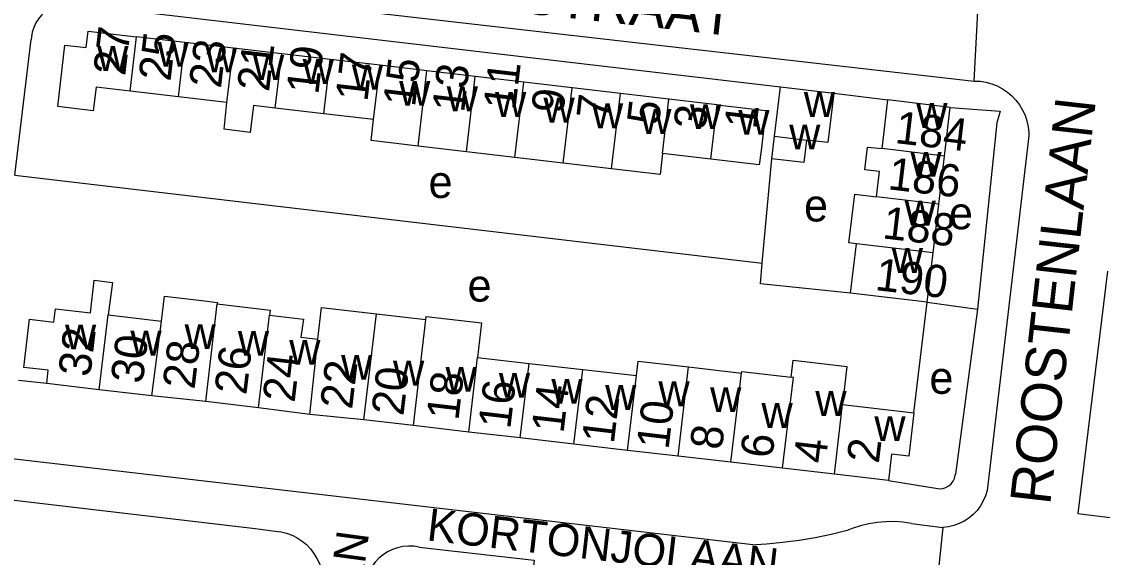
# Model space of a CAD drawing. Extents: x 161258 to 163262, y 380749 to 382054.
# Drawn here: x 162145.4 to 162279.3, y 380909.2 to 380975.6 of the extents above; entities that cross this region are included whole.
import ezdxf

# ---------------------------------------------------------------- set-up
doc = ezdxf.new("R2010")
doc.units = 0
for name, color, linetype in [('BLT_Basislijn', 7, 'Continuous'), ('BLT_Bebouwing', 7, 'Continuous'), ('BLT_Centroide', 7, 'Continuous'), ('BLT_Huisnummer', 7, 'Continuous'), ('BLT_Huisnummer_ tussenligend', 7, 'Continuous'), ('BLT_Onderverdeling_panden', 7, 'Continuous'), ('BLT_Straatnaam', 7, 'Continuous'), ('BLT_Straatnaam_verkleind', 7, 'Continuous'), ('BLT_Vlakafsluiter', 7, 'Continuous')]:
    doc.layers.add(name, color=color, linetype=linetype)

msp = doc.modelspace()

# ---------------------------------------------------------------- linework, layer by layer
at = {"layer": 'BLT_Basislijn'}
for p, q in [((162149.69, 380981.18), (162263.4, 380968.19)), ((162151.72, 380977.74), (162239.4, 380967.48)), ((162144.57, 380956.51), (162146.6, 380973.32)), ((162246, 380966.69), (162252.7, 380965.85)), ((162270.17, 380961.38), (162264.99, 380917.45)), ((162237.15, 380945.62), (162238.35, 380958.55)), ((162144.57, 380956.51), (162237.15, 380945.62)), ((162255.92, 380927.07), (162257.58, 380940.78)), ((162257.58, 380940.78), (162263.8, 380939.93)), ((162263.8, 380939.93), (162261.07, 380919.46)), ((162148.51, 380930.7), (162145, 380931.06)), ((162137.75, 380922.16), (162236.36, 380910.73)), ((162252.79, 380918.69), (162259.13, 380917.67)), ((162129.01, 380918.07), (162174.34, 380912.72)), ((162255.62, 380913.38), (162259.51, 380912.85)), ((162174.34, 380912.72), (162176.83, 380912.42))]:
    msp.add_line(p, q, dxfattribs=at)
for points in [[(162151.72, 380977.74), (162151.12, 380977.77), (162150.51, 380977.73), (162149.92, 380977.6), (162149.35, 380977.39), (162148.81, 380977.12), (162148.32, 380976.77), (162147.87, 380976.36), (162147.48, 380975.9), (162147.15, 380975.39), (162146.9, 380974.84), (162146.72, 380974.26), (162146.62, 380973.67), (162146.6, 380973.32)], [(162263.4, 380968.19), (162264.13, 380968.16), (162264.86, 380968.04), (162265.57, 380967.85), (162266.25, 380967.58), (162266.9, 380967.24), (162267.51, 380966.82), (162268.07, 380966.35), (162268.57, 380965.82), (162269.01, 380965.23), (162269.39, 380964.6), (162269.7, 380963.94), (162269.93, 380963.24), (162270.09, 380962.53), (162270.16, 380961.8), (162270.17, 380961.38)], [(162260.44, 380964.93), (162266.6, 380964.46), (162266.21, 380963.03), (162263.8, 380939.93)], [(162248.07, 380941.9), (162236.91, 380943.04), (162237.15, 380945.62)], [(162279.93, 380944.61), (162276.25, 380914.58), (162303.55, 380911.22)], [(162259.13, 380917.67), (162259.52, 380917.71), (162259.9, 380917.83), (162260.24, 380918.03), (162260.54, 380918.28), (162260.78, 380918.6), (162260.96, 380918.95), (162261.05, 380919.34), (162261.07, 380919.46)], [(162264.99, 380917.45), (162264.79, 380916.79), (162264.51, 380916.15), (162264.16, 380915.55), (162263.75, 380914.99), (162263.27, 380914.49), (162262.74, 380914.04), (162262.16, 380913.66), (162261.54, 380913.35), (162260.89, 380913.1), (162260.22, 380912.94), (162259.51, 380912.85)], [(162255.62, 380913.38), (162254.57, 380913.53), (162253.51, 380913.6), (162252.44, 380913.58), (162251.38, 380913.49), (162250.33, 380913.32), (162249.3, 380913.07), (162248.29, 380912.74), (162247.67, 380912.5)], [(162176.83, 380912.42), (162177.54, 380912.33), (162178.23, 380912.16), (162178.9, 380911.91), (162179.54, 380911.58), (162180.14, 380911.19), (162180.69, 380910.74), (162181.19, 380910.22), (162181.62, 380909.65), (162181.99, 380909.04), (162182.29, 380908.39), (162182.52, 380907.71), (162182.67, 380907.01), (162182.74, 380906.3), (162182.73, 380905.69)], [(162247.67, 380912.5), (162245.7, 380912), (162243.71, 380911.59), (162241.71, 380911.25), (162239.7, 380910.99), (162237.67, 380910.81), (162236.36, 380910.73)], [(162194.65, 380910.44), (162193.98, 380910.54), (162193.31, 380910.56), (162192.64, 380910.49), (162191.98, 380910.35), (162191.34, 380910.13), (162190.74, 380909.84), (162190.17, 380909.48), (162189.65, 380909.05), (162189.19, 380908.56), (162188.78, 380908.03), (162188.44, 380907.44), (162188.18, 380906.83), (162187.99, 380906.18), (162187.87, 380905.52), (162187.84, 380904.85), (162187.86, 380904.41)], [(162194.65, 380910.44), (162208.89, 380908.83), (162208.71, 380907.24), (162226.2, 380904.94), (162226.56, 380906.89), (162234.68, 380905.82), (162237.16, 380905.82)]]:
    msp.add_lwpolyline(points, dxfattribs=at)
at = {"layer": 'BLT_Bebouwing'}
for p, q in [((162165.63, 380972.97), (162159.64, 380973.67)), ((162171.63, 380972.27), (162165.63, 380972.97)), ((162177.62, 380971.57), (162171.63, 380972.27)), ((162183.62, 380970.87), (162177.62, 380971.57)), ((162189.8, 380970.14), (162183.62, 380970.87)), ((162195.61, 380969.46), (162189.8, 380970.14)), ((162201.6, 380968.76), (162195.61, 380969.46)), ((162207.6, 380968.06), (162201.6, 380968.76)), ((162213.59, 380967.36), (162207.6, 380968.06)), ((162164.84, 380966.24), (162158.85, 380966.94)), ((162219.59, 380966.66), (162213.59, 380967.36)), ((162225.58, 380965.95), (162219.59, 380966.66)), ((162238.68, 380961.34), (162239.4, 380967.48)), ((162239.4, 380967.48), (162246, 380966.69)), ((162170.84, 380965.54), (162164.84, 380966.24)), ((162231.58, 380965.25), (162225.58, 380965.95)), ((162260.44, 380964.93), (162252.7, 380965.85)), ((162182.83, 380964.14), (162176.83, 380964.84)), ((162189.01, 380963.41), (162182.83, 380964.14)), ((162259.72, 380958.9), (162260.44, 380964.93)), ((162238.35, 380958.55), (162238.68, 380961.34)), ((162200.51, 380959.43), (162194.51, 380960.13)), ((162206.5, 380958.73), (162200.51, 380959.43)), ((162212.5, 380958.03), (162206.5, 380958.73)), ((162230.79, 380958.52), (162224.79, 380959.22)), ((162259.02, 380952.92), (162259.72, 380958.9)), ((162218.49, 380957.33), (162212.5, 380958.03)), ((162258.3, 380946.89), (162259.02, 380952.92)), ((162248.07, 380941.9), (162248.8, 380948.02)), ((162257.58, 380940.78), (162258.3, 380946.89)), ((162156.12, 380939.21), (162162.73, 380938.43)), ((162189.35, 380939.34), (162195.49, 380938.63)), ((162201.87, 380933.94), (162208.26, 380933.2)), ((162208.26, 380933.2), (162214.9, 380932.44)), ((162214.9, 380932.44), (162221.55, 380931.68)), ((162228, 380932.76), (162234.58, 380932)), ((162155.02, 380929.93), (162148.51, 380930.7)), ((162161.54, 380929.16), (162155.02, 380929.93)), ((162168.21, 380928.46), (162161.54, 380929.16)), ((162174.76, 380927.71), (162168.21, 380928.46)), ((162247.1, 380928.11), (162255.92, 380927.07)), ((162181.09, 380926.85), (162174.76, 380927.71)), ((162187.8, 380926.2), (162181.09, 380926.85)), ((162193.94, 380925.49), (162187.8, 380926.2)), ((162200.78, 380924.69), (162193.94, 380925.49)), ((162207.17, 380923.96), (162200.78, 380924.69)), ((162213.81, 380923.19), (162207.17, 380923.96)), ((162220.46, 380922.42), (162213.81, 380923.19)), ((162226.72, 380921.69), (162220.46, 380922.42)), ((162233.24, 380920.94), (162226.72, 380921.69)), ((162239.67, 380920.2), (162233.24, 380920.94)), ((162246.08, 380919.46), (162239.67, 380920.2)), ((162252.79, 380918.69), (162246.08, 380919.46))]:
    msp.add_line(p, q, dxfattribs=at)
for points in [[(162158.85, 380966.94), (162154.62, 380967.44), (162154.28, 380964.5), (162149.87, 380965.02), (162150.76, 380972.64), (162153.4, 380972.33), (162153.64, 380974.38), (162159.64, 380973.67)], [(162246, 380966.69), (162245.27, 380960.56), (162242.61, 380960.88)], [(162176.83, 380964.84), (162174.12, 380965.15), (162173.73, 380961.83), (162170.5, 380962.21), (162170.84, 380965.54)], [(162231.58, 380965.25), (162237.57, 380964.55), (162236.99, 380959.59), (162236.78, 380957.82), (162230.79, 380958.52)], [(162251.99, 380959.81), (162252.11, 380960.85), (162252.7, 380965.85)], [(162194.51, 380960.13), (162188.7, 380960.82), (162189.01, 380963.41)], [(162242.61, 380960.88), (162242.28, 380958.08), (162238.35, 380958.55)], [(162251.28, 380953.83), (162251.65, 380956.98), (162249.84, 380957.19), (162250.17, 380959.98), (162251.99, 380959.81)], [(162224.79, 380959.22), (162224.49, 380956.62), (162218.49, 380957.33)], [(162248.8, 380948.02), (162247.89, 380948.12), (162248.6, 380954.15), (162251.28, 380953.83)], [(162148.51, 380930.7), (162148.7, 380932.34), (162145.69, 380932.69), (162146.4, 380938.67), (162149.4, 380938.32), (162149.6, 380939.98), (162153.94, 380939.48), (162154.41, 380943.5), (162156.66, 380943.24), (162156.12, 380939.21)], [(162162.73, 380938.43), (162163.1, 380941.53), (162168.06, 380940.94), (162169.66, 380940.75), (162169.64, 380940.57)], [(162257.58, 380940.78), (162252.61, 380941.36), (162248.07, 380941.9)], [(162169.64, 380940.57), (162176.18, 380939.8), (162176.11, 380939.16)], [(162182.08, 380936.2), (162182.54, 380940.12), (162189.35, 380939.34)], [(162176.11, 380939.16), (162180.33, 380938.66), (162180, 380936.43), (162182.08, 380936.2)], [(162195.49, 380938.63), (162195.53, 380939.01), (162202.38, 380938.23), (162201.87, 380933.94)], [(162221.55, 380931.68), (162221.76, 380933.47), (162228, 380932.76)], [(162240.72, 380931.49), (162240.97, 380933.58), (162247.64, 380932.8), (162247.1, 380928.11)], [(162234.58, 380932), (162234.6, 380932.19), (162240.72, 380931.49)], [(162255.92, 380927.07), (162255.29, 380921.69), (162253.17, 380921.94), (162252.79, 380918.69)]]:
    msp.add_lwpolyline(points, dxfattribs=at)
at = {"layer": 'BLT_Onderverdeling_panden'}
for p, q in [((162158.85, 380966.94), (162159.64, 380973.67)), ((162164.84, 380966.24), (162165.63, 380972.97)), ((162170.84, 380965.54), (162171.63, 380972.27)), ((162176.83, 380964.84), (162177.62, 380971.57)), ((162182.83, 380964.14), (162183.62, 380970.87)), ((162189.01, 380963.41), (162189.8, 380970.14)), ((162194.51, 380960.13), (162195.61, 380969.46)), ((162200.51, 380959.43), (162201.6, 380968.76)), ((162206.5, 380958.73), (162207.6, 380968.06)), ((162212.5, 380958.03), (162213.59, 380967.36)), ((162218.49, 380957.33), (162219.59, 380966.66)), ((162224.79, 380959.22), (162225.58, 380965.95)), ((162230.79, 380958.52), (162231.58, 380965.25)), ((162238.68, 380961.34), (162242.61, 380960.88)), ((162259.72, 380958.9), (162251.99, 380959.81)), ((162259.02, 380952.92), (162251.28, 380953.83)), ((162258.3, 380946.89), (162248.8, 380948.02)), ((162168.21, 380928.46), (162169.64, 380940.57)), ((162155.02, 380929.93), (162156.12, 380939.21)), ((162174.76, 380927.71), (162176.11, 380939.16)), ((162187.8, 380926.2), (162189.35, 380939.34)), ((162193.94, 380925.49), (162195.49, 380938.63)), ((162161.54, 380929.16), (162162.73, 380938.43)), ((162181.09, 380926.85), (162182.08, 380936.2)), ((162200.78, 380924.69), (162201.87, 380933.94)), ((162207.17, 380923.96), (162208.26, 380933.2)), ((162213.81, 380923.19), (162214.9, 380932.44)), ((162226.72, 380921.69), (162228, 380932.76)), ((162233.24, 380920.94), (162234.58, 380932)), ((162220.46, 380922.42), (162221.55, 380931.68)), ((162246.08, 380919.46), (162247.1, 380928.11))]:
    msp.add_line(p, q, dxfattribs=at)
msp.add_lwpolyline([(162239.67, 380920.2), (162241, 380931.46), (162240.72, 380931.49)], dxfattribs=at)
at = {"layer": 'BLT_Vlakafsluiter'}
for p, q in [((162263.4, 380968.19), (162263.86, 380976.81)), ((162259.51, 380912.85), (162258.96, 380907.71))]:
    msp.add_line(p, q, dxfattribs=at)

# ---------------------------------------------------------------- texts
at = {"layer": 'BLT_Centroide'}
for s, p in [('w', (162154.77, 380969.44)), ('w', (162162.23, 380969.95)), ('w', (162168.23, 380969.25)), ('w', (162174.06, 380968.33)), ('w', (162180.22, 380967.84)), ('w', (162186.31, 380967.14)), ('w', (162192.16, 380965.14)), ('w', (162198.06, 380964.45)), ('w', (162204.05, 380963.75)), ('w', (162242.3, 380963.75)), ('w', (162210.05, 380963.05)), ('w', (162216.05, 380962.34)), ('w', (162228.19, 380962.23)), ('w', (162256.22, 380962.38)), ('w', (162222.03, 380961.64)), ('w', (162234.17, 380961.53)), ('w', (162240.48, 380959.72)), ('w', (162255.5, 380956.34)), ('e', (162195.81, 380953.7)), ('e', (162242.32, 380950.79)), ('w', (162254.78, 380950.28)), ('e', (162260.27, 380949.82)), ('w', (162253.19, 380944.41)), ('e', (162200.64, 380940.86)), ('w', (162150.78, 380934.94)), ('w', (162158.88, 380934.17)), ('w', (162165.59, 380934.98)), ('w', (162172.19, 380934.14)), ('w', (162178.55, 380933.03)), ('w', (162184.98, 380931.17)), ('w', (162191.41, 380930.45)), ('w', (162197.91, 380929.7)), ('w', (162204.52, 380928.94)), ('e', (162257.85, 380929.43)), ('w', (162211.03, 380928.19)), ('w', (162217.69, 380927.44)), ('w', (162224.28, 380927.89)), ('w', (162230.69, 380927.16)), ('w', (162243.72, 380926.69)), ('w', (162237.05, 380925.2)), ('w', (162251.03, 380923.58))]:
    msp.add_text(s, height=4, dxfattribs=at).set_placement(p)
at = {"layer": 'BLT_Huisnummer'}
for s, rotation, p in [('27', 83.3228, (162158.23, 380968.75)), ('21', 83.3218, (162176.04, 380966.78)), ('17', 83.3188, (162188.23, 380965.55)), ('13', 83.3178, (162200.21, 380964.2)), ('9', 83.3243, (162212.49, 380964.08)), ('5', 83.3223, (162224.33, 380962.64)), ('1', 83.3156, (162236.4, 380962.13)), ('184', 353.2545, (162253.48, 380960.52)), ('190', 353.246, (162251.02, 380942.3)), ('32', 83.2669, (162153.9, 380931.44)), ('26', 83.2683, (162173.24, 380929.21)), ('22', 83.2656, (162186.33, 380927.42)), ('18', 83.2635, (162199.5, 380926.04)), ('14', 83.2702, (162212.52, 380924.46)), ('10', 83.2663, (162225.53, 380922.45)), ('6', 83.2644, (162238.39, 380921.34)), ('2', 83.2742, (162251.58, 380920.71))]:
    msp.add_text(s, height=4, rotation=rotation, dxfattribs=at).set_placement(p)
at = {"layer": 'BLT_Huisnummer_ tussenligend'}
for s, rotation, p in [('25', 83.3218, (162163.84, 380968.07)), ('23', 83.3218, (162170.09, 380967.2)), ('19', 83.3188, (162182.15, 380966.43)), ('15', 83.3178, (162194.13, 380964.9)), ('11', 83.3243, (162206.55, 380964.48)), ('7', 83.3223, (162218.08, 380963.32)), ('3', 83.3156, (162230.1, 380962.04)), ('186', 353.2545, (162252.61, 380954.79)), ('188', 353.2545, (162251.93, 380948.71)), ('30', 83.2683, (162160.4, 380930.6)), ('28', 83.2683, (162166.82, 380929.91)), ('24', 83.2656, (162179.21, 380928.27)), ('20', 83.2635, (162192.69, 380926.61)), ('16', 83.2702, (162205.93, 380924.98)), ('12', 83.2663, (162218.76, 380923.16)), ('8', 83.2644, (162232.14, 380922.39)), ('4', 83.2742, (162244.98, 380920.7))]:
    msp.add_text(s, height=4, rotation=rotation, dxfattribs=at).set_placement(p)
at = {"layer": 'BLT_Straatnaam'}
for s, rotation, p in [('HYACINTHSTRAAT', 353.6304, (162173.27, 380980.46)), ('ROOSTENLAAN', 83.5487, (162272.8, 380915.57))]:
    msp.add_text(s, height=5, rotation=rotation, dxfattribs=at).set_placement(p)
at = {"layer": 'BLT_Straatnaam_verkleind'}
for s, height, rotation, p in [('KORTONJOLAAN', 3.9999, 353.3865, (162195.49, 380911.28)), ('BOVISTENLAAN', 4, 82.3115, (162182.96, 380871.48))]:
    msp.add_text(s, height=height, rotation=rotation, dxfattribs=at).set_placement(p)

doc.saveas('drawing.dxf')
